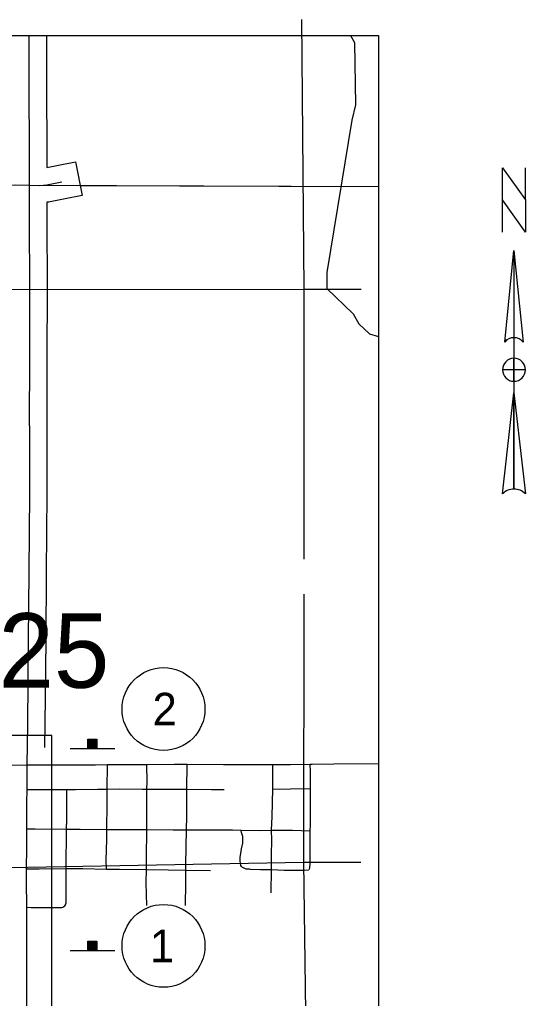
# Model space of a CAD drawing. Extents: x -2251611 to -2054719, y -2227156 to -2099355.
# Drawn here: x -2127401 to -2122741, y -2126976 to -2117964 of the extents above; entities that cross this region are included whole.
import ezdxf

# ---------------------------------------------------------------- set-up
doc = ezdxf.new("R2010")
doc.units = 0
for name, color, linetype in [('Default', 7, 'Continuous'), ('dsnCellsNorthArrow', 7, 'Continuous'), ('dsnTextFinalPlan', 7, 'Continuous'), ('dsnTextNote', 7, 'Continuous'), ('tdCoCityStreetMajor', 7, 'Continuous'), ('tdCoCityStreetMinor', 7, 'Continuous'), ('tdCoHydroRiver', 7, 'Continuous'), ('tdCoSecRteBand', 7, 'Continuous'), ('tdCoSectLinePart', 7, 'Continuous'), ('tdCoSectNmbr', 7, 'Continuous'), ('tdCoSurfAsphalt', 7, 'Continuous'), ('tdCoSurfConc', 7, 'Continuous'), ('tdCoSurfGravel', 7, 'Continuous'), ('tdCoTwpBndry', 7, 'Continuous'), ('tdCoTwpBndryShd', 7, 'Continuous')]:
    doc.layers.add(name, color=color, linetype=linetype)

msp = doc.modelspace()

# ---------------------------------------------------------------- linework, layer by layer
at = {"layer": 'Default'}
for p, q in [((-2127105.2, -2124556.4), (-2138233.4, -2124556.4)), ((-2127105.2, -2135027.8), (-2127105.2, -2124556.4))]:
    msp.add_line(p, q, dxfattribs=at)
at = {"layer": 'dsnCellsNorthArrow'}
for p, q in [((-2122846.9, -2120089.7), (-2122762.4, -2120934.8)), ((-2122846.9, -2120089.7), (-2122846.9, -2122287)), ((-2122931.4, -2120934.8), (-2122931.4, -2120934.8)), ((-2122928.1, -2120927), (-2122912.4, -2120909.4)), ((-2122846.9, -2121294), (-2122846.9, -2121294)), ((-2122952.5, -2122329.3), (-2122846.9, -2121399.6))]:
    msp.add_line(p, q, dxfattribs=at)
msp.add_lwpolyline([(-2122741.2, -2119920.7), (-2122952.5, -2119624.9), (-2122952.5, -2119329.1), (-2122741.2, -2119624.9)], close=True, dxfattribs=at)
for points in [[(-2122952.5, -2119920.7), (-2122952.5, -2119329.1), (-2122741.2, -2119624.9), (-2122741.2, -2119329.1)], [(-2122931.4, -2120934.8), (-2122846.9, -2120089.7), (-2122846.9, -2120892.5)], [(-2122741.2, -2121188.3), (-2122846.9, -2121188.3), (-2122846.9, -2121082.7)], [(-2122846.9, -2121294), (-2122846.9, -2121188.3), (-2122952.5, -2121188.3)], [(-2122846.9, -2122287), (-2122846.9, -2121399.6), (-2122741.2, -2122329.3)]]:
    msp.add_lwpolyline(points, dxfattribs=at)
for centre, radius, start, end in [((-2122846.8, -2120998.2), 105.7, 90.02039, 143.12574), ((-2122846.8, -2120998.1), 105.6, 36.84806, 90.02184), ((-2122846.9, -2121188.3), 105.6, 90, 180), ((-2122846.9, -2121188.3), 105.7, 360, 90), ((-2122846.9, -2121188.3), 105.6, 180, 270), ((-2122846.9, -2121188.3), 105.7, 270, 360), ((-2122846.9, -2122440.1), 153.1, 89.98939, 133.61895), ((-2122846.9, -2122440.2), 153.2, 46.40206, 90.00064)]:
    msp.add_arc(centre, radius, start, end, dxfattribs=at)
at = {"layer": 'dsnTextFinalPlan'}
for p, q in [((-2126772.3, -2124593.7), (-2126688.5, -2124593.7)), ((-2126935.2, -2124673.6), (-2126522.7, -2124673.6)), ((-2126688.5, -2124598.5), (-2126772.3, -2124598.5)), ((-2126772.3, -2124601.9), (-2126688.5, -2124601.9)), ((-2126688.5, -2124606.7), (-2126772.3, -2124606.7)), ((-2126772.3, -2124610), (-2126688.5, -2124609.8)), ((-2126688.5, -2124616.2), (-2126772.3, -2124616.5)), ((-2126772.3, -2124619.6), (-2126688.5, -2124619.6)), ((-2126688.5, -2124626.1), (-2126772.3, -2124626.1)), ((-2126772.3, -2124631.7), (-2126688.5, -2124631.7)), ((-2126688.5, -2124636.5), (-2126772.3, -2124636.8)), ((-2126772.3, -2124639.8), (-2126688.5, -2124639.8)), ((-2126688.5, -2124643.8), (-2126772.3, -2124643.8)), ((-2126772.3, -2124648.8), (-2126688.5, -2124648.8)), ((-2126688.5, -2124651.9), (-2126772.3, -2124651.9)), ((-2126772.3, -2124655.3), (-2126688.5, -2124655.3)), ((-2126688.5, -2124659.3), (-2126772.3, -2124659.3)), ((-2126772.3, -2124663.2), (-2126688.5, -2124663.2)), ((-2126688.5, -2124667.4), (-2126772.3, -2124667.4)), ((-2126772.3, -2126456.1), (-2126688.5, -2126456.1)), ((-2126688.5, -2126460.9), (-2126772.3, -2126460.9)), ((-2126772.3, -2126464.2), (-2126688.5, -2126464.2)), ((-2126688.5, -2126469), (-2126772.3, -2126469)), ((-2126772.3, -2126472.4), (-2126688.5, -2126472.1)), ((-2126688.5, -2126478.6), (-2126772.3, -2126478.9)), ((-2126772.3, -2126482), (-2126688.5, -2126482)), ((-2126935.2, -2126536), (-2126522.7, -2126536)), ((-2126688.5, -2126488.4), (-2126772.3, -2126488.4)), ((-2126772.3, -2126494), (-2126688.5, -2126494)), ((-2126688.5, -2126498.8), (-2126772.3, -2126499.1)), ((-2126772.3, -2126502.2), (-2126688.5, -2126502.2)), ((-2126688.5, -2126506.1), (-2126772.3, -2126506.1)), ((-2126772.3, -2126511.2), (-2126688.5, -2126511.2)), ((-2126688.5, -2126514.3), (-2126772.3, -2126514.3)), ((-2126772.3, -2126517.7), (-2126688.5, -2126517.7)), ((-2126688.5, -2126521.6), (-2126772.3, -2126521.6)), ((-2126772.3, -2126525.5), (-2126688.5, -2126525.5)), ((-2126688.5, -2126529.8), (-2126772.3, -2126529.8))]:
    msp.add_line(p, q, dxfattribs=at)
for points in [[(-2126688.5, -2124672.2), (-2126772.9, -2124672.2), (-2126772.9, -2124587.8), (-2126688.5, -2124587.8)], [(-2126688.5, -2126534.5), (-2126772.9, -2126534.5), (-2126772.9, -2126450.2), (-2126688.5, -2126450.2)]]:
    msp.add_lwpolyline(points, close=True, dxfattribs=at)
at = {"layer": 'dsnTextNote'}
msp.add_lwpolyline([(-2138305.1, -2118109.7), (-2124095.9, -2118109.7), (-2124095.9, -2144315.9), (-2146959.9, -2144315.9), (-2146959.9, -2118109.7), (-2138305.1, -2118109.7)], dxfattribs=at)
for centre in [(-2126075.2, -2124312.1), (-2126075.2, -2126492.5)]:
    msp.add_circle(centre, 381.4, dxfattribs=at)
at = {"layer": 'tdCoCityStreetMajor'}
for points in [[(-2125860.8, -2125266.6), (-2125859.7, -2125085.7), (-2125859.4, -2125050), (-2125857.6, -2124820.7)], [(-2125863.2, -2125423.8), (-2125861, -2125298), (-2125860.8, -2125266.6)], [(-2127332.7, -2125416), (-2127256.8, -2125413.9), (-2126967.3, -2125417.5), (-2126841.4, -2125419.1), (-2126596.3, -2125419.9)], [(-2126596.3, -2125419.9), (-2126453.4, -2125420.4), (-2126229.4, -2125422.2), (-2125986, -2125424.3), (-2125863.2, -2125423.9)]]:
    msp.add_lwpolyline(points, dxfattribs=at)
at = {"layer": 'tdCoCityStreetMinor'}
for p, q in [((-2126594.1, -2125049.5), (-2126591.9, -2124823.8)), ((-2124905.6, -2125047.2), (-2124720.9, -2125043.5)), ((-2126971.1, -2125781.5), (-2126967.3, -2125417.5)), ((-2125544.6, -2125423.9), (-2125440.3, -2125425.5)), ((-2125084.8, -2126002.6), (-2125081.7, -2125790.1)), ((-2126984.2, -2126124), (-2126983.6, -2126123.2))]:
    msp.add_line(p, q, dxfattribs=at)
for points in [[(-2126228.1, -2126119.6), (-2126233.4, -2125911.2), (-2126232.2, -2125789.7), (-2126230.7, -2125633.9), (-2126229.4, -2125472.4), (-2126229.4, -2125422.2), (-2126229.4, -2125337), (-2126229.4, -2125096.1), (-2126228.3, -2125048.6), (-2126226.8, -2124984.2), (-2126229.4, -2124821.9)], [(-2125081.7, -2125790.1), (-2125080, -2125655.2), (-2125076.6, -2125517.8), (-2125080.8, -2125426.4), (-2125074, -2125301.8), (-2125068.9, -2125047.2), (-2125069.3, -2124933.4), (-2125068.6, -2124822.4)], [(-2124730.8, -2125790.2), (-2124724.2, -2125743.3), (-2124724.2, -2125519.3), (-2124722.6, -2125433.3), (-2124721.6, -2125378.7), (-2124720.3, -2125174.3), (-2124720.9, -2125043.5), (-2124721.6, -2124886.5), (-2124723.9, -2124819.5)], [(-2127331.6, -2125051.3), (-2127204.7, -2125053.2), (-2127038.3, -2125053.2), (-2126991, -2125053.2), (-2126966.4, -2125053.2), (-2126884.3, -2125052.4), (-2126682.8, -2125050.3), (-2126644.5, -2125050), (-2126594.1, -2125049.5), (-2126478.1, -2125048), (-2126268.6, -2125048.5), (-2126228.3, -2125048.6), (-2125941.7, -2125049.3), (-2125922.1, -2125049.4), (-2125859.4, -2125050), (-2125634, -2125052.1)], [(-2126967.3, -2125417.5), (-2126966.4, -2125329.2), (-2126966.4, -2125053.2)], [(-2126596.3, -2125419.9), (-2126595.3, -2125180.8), (-2126594.1, -2125049.5)], [(-2125634, -2125052.1), (-2125555.2, -2125052.8), (-2125517.2, -2125053.2)], [(-2125068.9, -2125047.2), (-2125006.8, -2125049.3), (-2124905.6, -2125047.2)], [(-2126599.2, -2125785.2), (-2126601.8, -2125704.2), (-2126596.6, -2125514.1), (-2126596.3, -2125419.9)], [(-2125872.7, -2126119.6), (-2125868.8, -2125916.5), (-2125868.8, -2125794.3), (-2125868.8, -2125740.7), (-2125863.2, -2125423.9), (-2125863.2, -2125423.8)], [(-2125863.2, -2125423.9), (-2125601.8, -2125423), (-2125544.6, -2125423.9)], [(-2125440.3, -2125425.5), (-2125362.4, -2125426.8), (-2125193, -2125429.5), (-2125080.8, -2125426.4)], [(-2125338.2, -2125774.3), (-2125348.9, -2125770.6), (-2125356.1, -2125761.3), (-2125363.4, -2125752), (-2125366.2, -2125731.1), (-2125368.5, -2125713.9), (-2125368.5, -2125676.7), (-2125363.6, -2125643.2), (-2125357.2, -2125599.4), (-2125345.3, -2125546.3), (-2125344.4, -2125528.1), (-2125343.8, -2125513.8), (-2125344.7, -2125500.2), (-2125345.8, -2125483.9), (-2125353.7, -2125456.7), (-2125362.4, -2125426.8)], [(-2125080.8, -2125426.4), (-2124888.3, -2125428.2), (-2124722.6, -2125433.3)], [(-2127336.1, -2125783.7), (-2127220.3, -2125782.3), (-2126971.1, -2125781.5), (-2126816.7, -2125781), (-2126599.2, -2125785.2), (-2126479.4, -2125787.5), (-2126232.2, -2125789.7), (-2126032.8, -2125791.5), (-2125868.8, -2125794.3), (-2125640.7, -2125798.4)], [(-2126983.6, -2126123.2), (-2126978, -2126115.3), (-2126973.9, -2126105.5), (-2126972.2, -2126095), (-2126972.9, -2126084.4), (-2126971.6, -2125830.5), (-2126971.1, -2125781.5)], [(-2125338.2, -2125774.3), (-2125335.5, -2125775.2), (-2125324.1, -2125779.1), (-2125315.9, -2125781.9), (-2125303, -2125782.9), (-2125287.4, -2125784.1), (-2125276.3, -2125784.9), (-2125181.3, -2125790.2), (-2125081.7, -2125790.1), (-2124965.1, -2125794.1), (-2124777.6, -2125796.7), (-2124735.4, -2125790.8)], [(-2127334.5, -2126137.3), (-2127293.2, -2126137.8), (-2127022.4, -2126139.1), (-2127011.8, -2126138.8), (-2127001.5, -2126136), (-2126992.1, -2126131), (-2126984.2, -2126124)]]:
    msp.add_lwpolyline(points, dxfattribs=at)
at = {"layer": 'tdCoHydroRiver'}
msp.add_lwpolyline([(-2124353.5, -2118109.7), (-2124316.6, -2118173.9), (-2124305.2, -2118749), (-2124339.9, -2118890.8), (-2124569.9, -2120291.1), (-2124569.5, -2120441.1), (-2124327.3, -2120673.8), (-2124277.2, -2120765.4), (-2124176.9, -2120856.8), (-2124095.9, -2120881.5)], dxfattribs=at)
at = {"layer": 'tdCoSecRteBand'}
msp.add_lwpolyline([(-2127153.5, -2118109.7), (-2127153.5, -2118500.4), (-2127150.9, -2119263.1), (-2127150.9, -2119263.4), (-2127150.9, -2119263.7), (-2127150.9, -2119325.1), (-2127042, -2119303.7), (-2126886.6, -2119273.2), (-2126825.6, -2119584.1), (-2126981, -2119614.6), (-2127120.3, -2119641.9), (-2127130.5, -2119643.9), (-2127140.9, -2119644.6), (-2127150.9, -2119645.2), (-2127150.9, -2119647.1), (-2127150.9, -2119789.2), (-2127147, -2120451.5), (-2127147, -2120452.2), (-2127147, -2120452.8), (-2127148.3, -2121068.7), (-2127149.5, -2121667.8), (-2127148.3, -2121670.3), (-2127148.3, -2121707.7), (-2127148.3, -2122324.9), (-2127148.3, -2122325.6), (-2127148.3, -2122326.3), (-2127154.8, -2123051.5), (-2127160, -2123673.8), (-2127160, -2123674), (-2127160, -2123674.1), (-2127167.8, -2124452.7), (-2127169.8, -2124666)], dxfattribs=at)
at = {"layer": 'tdCoSectLinePart'}
for points in [[(-2124804, -2117963.8), (-2124782.8, -2120445.7)], [(-2129911.8, -2120449.8), (-2124782.8, -2120445.7)], [(-2124782.8, -2120445.7), (-2124783.5, -2122933.1)], [(-2124782.8, -2120445.7), (-2124254.9, -2120444.4)], [(-2124783.6, -2123253.1), (-2124784.3, -2125720.6)], [(-2128512.6, -2125790.4), (-2124784.3, -2125720.6)], [(-2124784.3, -2125720.6), (-2124256.3, -2125720.4)], [(-2124784.3, -2125720.6), (-2124713.8, -2131016.1)]]:
    msp.add_lwpolyline(points, dxfattribs=at)
at = {"layer": 'tdCoSurfAsphalt'}
msp.add_line((-2124707, -2124819.2), (-2124706.9, -2124819.2), dxfattribs=at)
for points in [[(-2132366.6, -2124806.1), (-2132201.4, -2124806.2), (-2131457.9, -2124815.3), (-2130965.8, -2124817.9), (-2130051.7, -2124829.6), (-2129004.8, -2124832.2), (-2128055.6, -2124828.3), (-2127329.6, -2124825.1)], [(-2127329.6, -2124825.1), (-2127174.1, -2124824.4), (-2126700.1, -2124824.4), (-2126591.9, -2124823.8), (-2126229.4, -2124821.9), (-2125972.3, -2124820.5), (-2125857.6, -2124820.7), (-2125523.2, -2124821.3), (-2125424.5, -2124821.5), (-2125379, -2124821.6), (-2125068.6, -2124822.4), (-2124906.2, -2124821.1), (-2124723.9, -2124819.5), (-2124707, -2124819.2)], [(-2124706.9, -2124819.2), (-2124506.1, -2124815.3), (-2124095.9, -2124813.9)]]:
    msp.add_lwpolyline(points, dxfattribs=at)
at = {"layer": 'tdCoSurfConc'}
msp.add_lwpolyline([(-2127333.8, -2127473), (-2127332.7, -2126909.5), (-2127332.7, -2126259.7), (-2127334.5, -2126137.3), (-2127338, -2125892.6), (-2127336.1, -2125783.7), (-2127332.7, -2125586.6), (-2127332.7, -2125416), (-2127332.7, -2125176.4), (-2127331.6, -2125051.3), (-2127329.6, -2124825.1)], dxfattribs=at)
at = {"layer": 'tdCoSurfGravel'}
for points in [[(-2127309.3, -2119488.7), (-2127309.3, -2119263.7), (-2127311.9, -2118500.6), (-2127311.9, -2118109.7)], [(-2132568.8, -2119496.4), (-2132564.3, -2119492.5), (-2132555.6, -2119487.7), (-2132546.1, -2119484.8), (-2132536.2, -2119483.9), (-2132257.6, -2119486.5), (-2131124.8, -2119487.8), (-2129710.7, -2119490.4), (-2128576.6, -2119487.8), (-2127436, -2119486.5), (-2127309.3, -2119488.7)], [(-2127329.6, -2124825.1), (-2127326.2, -2124451.2), (-2127318.4, -2123672.5), (-2127313.2, -2123050.1), (-2127306.7, -2122324.9), (-2127306.7, -2121707.7), (-2127308, -2121705.1), (-2127306.7, -2121068.4), (-2127305.4, -2120452.5), (-2127309.3, -2119789.7), (-2127309.3, -2119488.7)], [(-2127309.3, -2119488.7), (-2127213.3, -2119490.4), (-2127150.8, -2119486.5), (-2127011.5, -2119459.1)]]:
    msp.add_lwpolyline(points, dxfattribs=at)
at = {"layer": 'tdCoTwpBndry'}
msp.add_lwpolyline([(-2126845.8, -2119490.4), (-2124095.9, -2119500.8)], dxfattribs=at)
at = {"layer": 'tdCoTwpBndryShd'}
msp.add_lwpolyline([(-2146959.9, -2119431.7), (-2143089.2, -2119427), (-2137865.5, -2119459.5), (-2132584.4, -2119484.2), (-2127311.1, -2119488.7), (-2124095.9, -2119500.8)], dxfattribs=at)

# ---------------------------------------------------------------- texts
at = {"layer": 'dsnTextNote'}
for s, p in [('2', (-2126175.5, -2124462.1)), ('1', (-2126200.3, -2126642.5))]:
    msp.add_text(s, height=300, dxfattribs=at).set_placement(p)
at = {"layer": 'tdCoSectNmbr'}
msp.add_text('25', height=686.4, rotation=0.02098, dxfattribs=at).set_placement((-2127594.8, -2124116.1))

doc.saveas('drawing.dxf')
